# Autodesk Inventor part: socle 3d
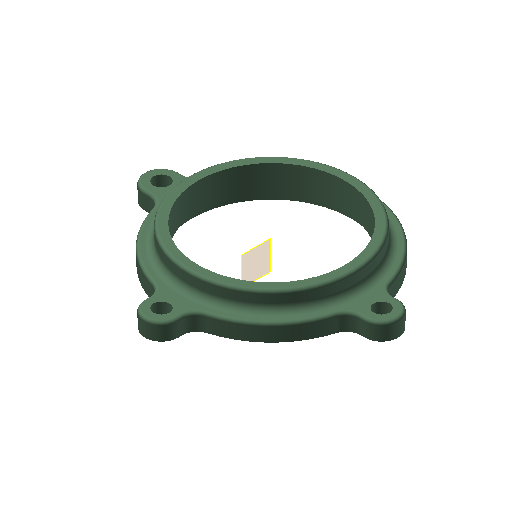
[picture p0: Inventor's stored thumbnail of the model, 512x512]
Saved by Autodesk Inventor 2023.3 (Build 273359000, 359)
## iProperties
Shininess: 21.0
Length Units: 11269
Angle Units: 11279
Time Units: 11290
Mass Units: 11283
Length Display Precision: 3
Angle Display Precision: 2
Created: 2001-10
Part Number: socle 3d
Material: Générique
Document SubType Name: Proxy Part
Designer: ajt
Density: 1 g/cm^3
Appearance: Caoutchouc - Vert
Density: 0.0
Volumn: 0.0
Area: 0.0
PropertySet Name: Model Information
Control State: 0
Master: False
Checked Out: False
Author: ajt
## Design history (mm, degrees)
feature "LinkedPart1"
node "Solide1"
node "Corps solides"
node "Corps surfaciques"
